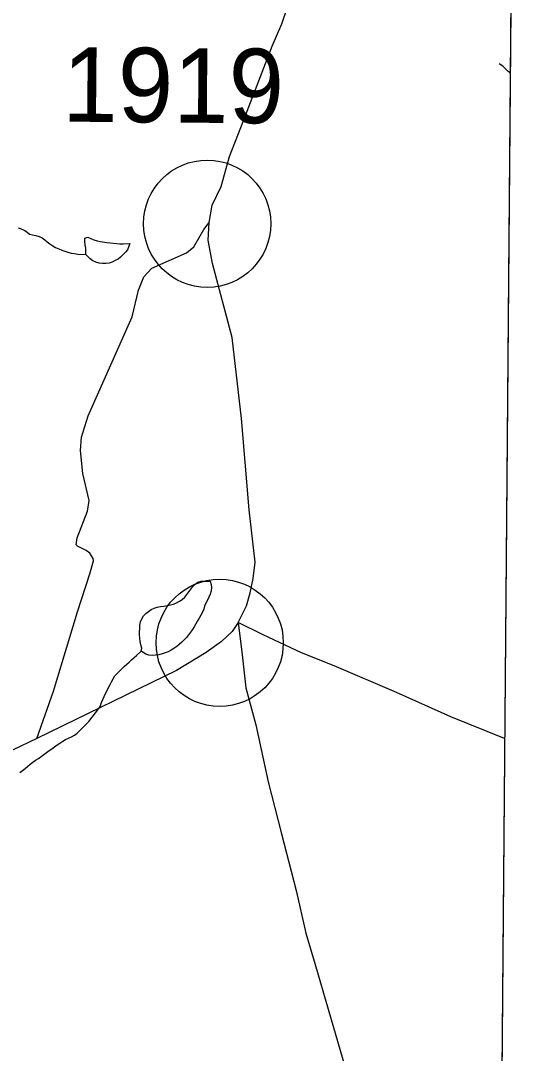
# Model space of a CAD drawing. Extents: x 1379453 to 1387082, y 594364 to 596664.
# Drawn here: x 1380647.4 to 1380745.8, y 596071.5 to 596276.1 of the extents above; entities that cross this region are included whole.
import ezdxf

# ---------------------------------------------------------------- set-up
doc = ezdxf.new("R2010")
doc.units = 0
for name, color, linetype in [('Old_Level_1', 7, 'Continuous'), ('Old_Level_32', 7, 'Continuous'), ('Old_Level_35', 7, 'Continuous'), ('Old_Level_62', 7, 'Continuous'), ('Old_Level_8', 7, 'Continuous'), ('Sheet Clip Boundary CELL', 7, 'Continuous')]:
    doc.layers.add(name, color=color, linetype=linetype)

msp = doc.modelspace()

# ---------------------------------------------------------------- linework, layer by layer
at = {"layer": 'Old_Level_1'}
msp.add_line((1380745.81, 596434.81), (1380740.66, 595820.56), dxfattribs=at)
at = {"layer": 'Old_Level_32'}
for points in [[(1380690.45, 596156.89), (1380692.15, 596160.17), (1380692.86, 596162.71), (1380693.47, 596165.59), (1380693.82, 596168.85), (1380692.68, 596179.21), (1380691.15, 596197.29), (1380689.28, 596213.3), (1380685.42, 596228.02), (1380684.56, 596232.6), (1380684.72, 596236.11), (1380685.33, 596239.56), (1380687.11, 596243.25), (1380688.77, 596249.19), (1380691.61, 596256.45), (1380697.2, 596271.02), (1380699.14, 596275.49), (1380701.23, 596281.75), (1380703.91, 596288.62), (1380706.19, 596292.32), (1380709.11, 596295.66), (1380711.61, 596297.12), (1380714.63, 596298.61)], [(1380690.45, 596156.89), (1380689.31, 596155.05), (1380687.19, 596153.09), (1380684.16, 596150.95), (1380678.29, 596147.37), (1380650.57, 596133.86), (1380636.43, 596127.15), (1380632.33, 596124.88), (1380623.16, 596118.7), (1380613.12, 596110.73), (1380610.48, 596107.63), (1380609.3, 596105.92)], [(1380743.29, 596133.89), (1380732.64, 596138.19), (1380721.83, 596142.97), (1380709.52, 596148.29), (1380703.04, 596150.83), (1380695.42, 596154.39), (1380690.45, 596156.89)], [(1380690.45, 596156.89), (1380691.25, 596150.45), (1380692.03, 596143.95), (1380693.97, 596136.6), (1380696.43, 596125.28), (1380699.09, 596114.97), (1380701.97, 596103.75), (1380703.91, 596095.29), (1380705.73, 596089.1), (1380708.34, 596080.29), (1380711.67, 596068.72), (1380714.14, 596052.46)]]:
    msp.add_lwpolyline(points, dxfattribs=at)
for centre in [(1380684.35, 596235.87), (1380686.82, 596152.84)]:
    msp.add_circle(centre, 12.61, dxfattribs=at)
at = {"layer": 'Old_Level_35'}
msp.add_lwpolyline([(1380650.57, 596133.86), (1380653.87, 596143.28), (1380658.64, 596158.99), (1380661.11, 596166.52), (1380661.82, 596169.06), (1380661.76, 596169.54), (1380661.07, 596170.61), (1380660.37, 596171.1), (1380658.63, 596171.96), (1380658.4, 596172.28), (1380658.6, 596173.64), (1380660.59, 596178.94), (1380660.97, 596181.01), (1380659.69, 596186.41), (1380659.26, 596190.91), (1380659.41, 596193.55), (1380660.75, 596197.83), (1380669.48, 596217.44), (1380670.76, 596222.68), (1380671.8, 596225.37), (1380673.39, 596227.05), (1380680.27, 596230.13), (1380681.7, 596231.31), (1380683.68, 596234.72), (1380684.72, 596236.11)], dxfattribs=at)
at = {"layer": 'Old_Level_62'}
msp.add_line((1380670.34, 596150.35), (1380671.23, 596151.16), dxfattribs=at)
for points in [[(1380744.39, 596265.72), (1380744.35, 596265.76), (1380743.85, 596266.19), (1380743.37, 596266.64), (1380742.91, 596267.11), (1380742.23, 596267.53)], [(1380646.86, 596235.06), (1380647.49, 596234.87), (1380648.08, 596234.6), (1380648.63, 596234.23), (1380649.11, 596233.79), (1380649.74, 596233.64), (1380650.4, 596233.52), (1380651.03, 596233.35), (1380651.61, 596233.06), (1380652.14, 596232.68), (1380652.66, 596232.27), (1380653.18, 596231.86), (1380653.73, 596231.5), (1380654.31, 596231.19), (1380654.91, 596230.91), (1380655.51, 596230.65), (1380656.12, 596230.42), (1380656.75, 596230.22), (1380657.39, 596230.05), (1380658.03, 596229.94), (1380658.68, 596229.86), (1380660.27, 596229.74)], [(1380660.27, 596229.74), (1380660.31, 596230.4), (1380660.29, 596231.05), (1380660.19, 596231.7), (1380660.09, 596232.36), (1380660.12, 596232.99), (1380660.7, 596233.21), (1380661.3, 596232.97), (1380661.9, 596232.7), (1380662.52, 596232.45), (1380663.15, 596232.33), (1380664.45, 596232.15), (1380667.03, 596231.9), (1380667.68, 596231.9), (1380669.02, 596231.94), (1380668.53, 596230.72), (1380668.12, 596230.21), (1380667.19, 596229.27), (1380666.68, 596228.87), (1380666.1, 596228.55), (1380665.51, 596228.27), (1380664.89, 596228.04), (1380664.23, 596227.98), (1380663.57, 596227.97), (1380662.92, 596228.05), (1380662.3, 596228.25), (1380661.7, 596228.53), (1380661.15, 596228.89), (1380660.27, 596229.74)], [(1380671.23, 596151.16), (1380671.37, 596151.81), (1380671.22, 596152.44), (1380671.05, 596153.08), (1380670.98, 596153.73), (1380670.96, 596154.39), (1380670.96, 596155.05), (1380670.97, 596155.7), (1380671.01, 596156.36), (1380671.12, 596157), (1380671.38, 596157.61), (1380671.72, 596158.17), (1380672.18, 596158.64), (1380672.69, 596159.05), (1380673.24, 596159.42), (1380673.83, 596159.7), (1380674.45, 596159.9), (1380675.1, 596160.03), (1380675.75, 596160.13), (1380676.4, 596160.23), (1380677.05, 596160.35), (1380677.67, 596160.52), (1380678.29, 596160.77), (1380678.87, 596161.09), (1380679.41, 596161.45), (1380679.9, 596161.9), (1380680.31, 596162.4), (1380680.7, 596162.94), (1380681.09, 596163.48), (1380681.49, 596164), (1380681.93, 596164.47), (1380682.5, 596164.83), (1380683.12, 596165.04), (1380683.76, 596165.08), (1380684.92, 596165.05), (1380685.13, 596164.42), (1380685.22, 596163.78), (1380685.11, 596163.13), (1380684.92, 596162.5), (1380684.67, 596161.89), (1380684.39, 596161.29), (1380684.09, 596160.71), (1380683.81, 596160.11), (1380683.67, 596159.49), (1380683.39, 596158.9), (1380683.09, 596158.31), (1380682.77, 596157.73), (1380682.44, 596157.17), (1380682.11, 596156.6), (1380681.77, 596156.03), (1380681.41, 596155.48), (1380681.04, 596154.94), (1380680.64, 596154.42), (1380680.22, 596153.91), (1380679.78, 596153.43), (1380679.31, 596152.96), (1380678.82, 596152.53), (1380678.3, 596152.13), (1380677.76, 596151.74), (1380677.21, 596151.39), (1380676.63, 596151.08), (1380676.02, 596150.83), (1380675.39, 596150.65), (1380674.75, 596150.48), (1380674.1, 596150.39), (1380673.44, 596150.35), (1380672.78, 596150.38), (1380672.18, 596150.6), (1380671.23, 596151.16)], [(1380647.22, 596127.16), (1380647.74, 596127.57), (1380648.25, 596127.97), (1380648.77, 596128.38), (1380649.29, 596128.77), (1380649.82, 596129.17), (1380650.35, 596129.56), (1380650.88, 596129.95), (1380651.41, 596130.33), (1380651.94, 596130.72), (1380652.48, 596131.1), (1380653.02, 596131.48), (1380653.55, 596131.85), (1380654.1, 596132.23), (1380654.63, 596132.61), (1380655.17, 596132.98), (1380655.71, 596133.35), (1380656.26, 596133.71), (1380656.86, 596133.98), (1380657.48, 596134.23), (1380658.05, 596134.54), (1380658.55, 596134.96), (1380660.87, 596137.24), (1380662.88, 596139.81), (1380663.17, 596140.38), (1380663.4, 596141), (1380663.65, 596141.61), (1380663.94, 596142.21), (1380664.22, 596142.8), (1380664.51, 596143.39), (1380664.81, 596143.97), (1380665.1, 596144.56), (1380665.41, 596145.14), (1380665.72, 596145.72), (1380666.05, 596146.28), (1380666.47, 596146.79), (1380666.95, 596147.25), (1380667.43, 596147.69), (1380667.9, 596148.14), (1380668.39, 596148.58), (1380668.88, 596149.02), (1380669.37, 596149.47), (1380669.85, 596149.91), (1380670.34, 596150.35)]]:
    msp.add_lwpolyline(points, dxfattribs=at)
at = {"layer": 'Sheet Clip Boundary CELL'}
msp.add_lwpolyline([(1379993.85, 596441.11), (1380745.81, 596434.81), (1380742.6, 596052.18), (1380696.17, 596052.63), (1380694.49, 595820.94), (1379988.71, 595826.86)], close=True, dxfattribs=at)

# ---------------------------------------------------------------- texts
at = {"layer": 'Old_Level_8'}
msp.add_text('1919', height=14.764, rotation=359.52, dxfattribs=at).set_placement((1380655.59, 596256.1))

doc.saveas('drawing.dxf')
